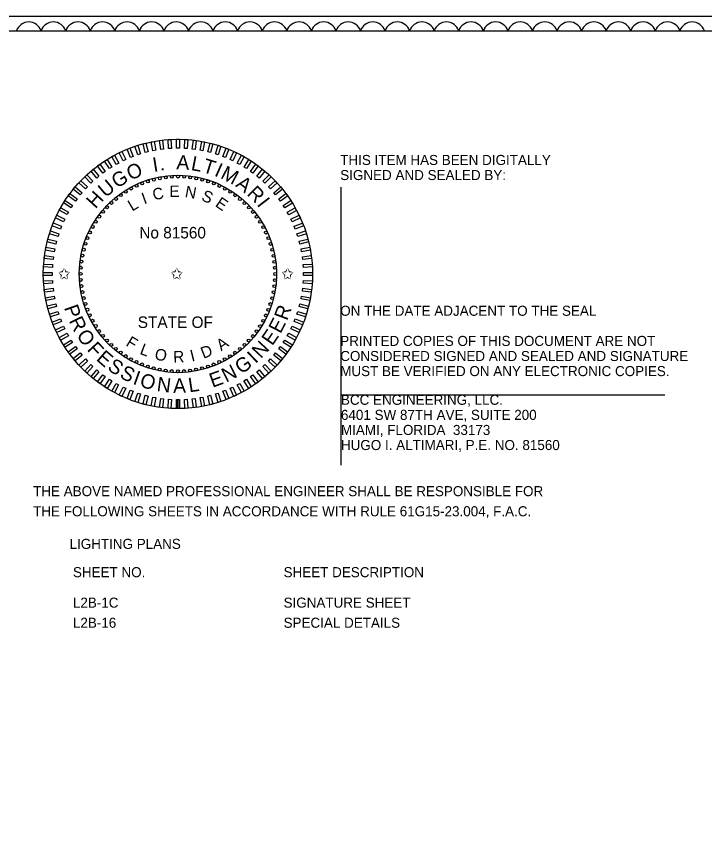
# Model space of a CAD drawing. Extents: x -811.3 to -790.1, y -2211.9 to -2188.9.
# Drawn here: x -802.91 to -798.12, y -2207.1 to -2201.34 of the extents above; entities that cross this region are included whole.
import ezdxf

# ---------------------------------------------------------------- set-up
doc = ezdxf.new("R2010")
doc.units = 0
for name, color, linetype in [('Cloud_dp', 7, 'Continuous'), ('Logo_dp', 7, 'Continuous'), ('NonPlottingEle_dp', 7, 'Continuous'), ('PlotBorder_dp', 7, 'Continuous'), ('ScratchEle_dp', 7, 'Continuous'), ('SheetBorder_dp', 7, 'Continuous'), ('TextMisc', 7, 'Continuous'), ('TextNotes', 7, 'Continuous')]:
    doc.layers.add(name, color=color, linetype=linetype)

msp = doc.modelspace()

# ---------------------------------------------------------------- linework, layer by layer
at = {"layer": 'Cloud_dp'}
for centre in [(-802.8286, -2201.467), (-802.6575, -2201.467), (-802.4863, -2201.467), (-802.3152, -2201.467), (-802.1441, -2201.467), (-801.973, -2201.467), (-801.8018, -2201.467), (-801.6307, -2201.467), (-801.4596, -2201.467), (-801.2885, -2201.467), (-801.1174, -2201.467), (-800.9462, -2201.467), (-800.7751, -2201.467), (-800.604, -2201.467), (-800.4329, -2201.467), (-800.2617, -2201.467), (-800.0906, -2201.467), (-799.9195, -2201.467), (-799.7484, -2201.467), (-799.5772, -2201.467), (-799.4061, -2201.467), (-799.235, -2201.467), (-799.0639, -2201.467), (-798.8928, -2201.467), (-798.7216, -2201.467), (-798.5505, -2201.467), (-798.3794, -2201.467), (-798.2083, -2201.467)]:
    msp.add_arc(centre, 0.0897, 17.5, 162.5, dxfattribs=at)
at = {"layer": 'Logo_dp'}
for p, q in [((-801.8001, -2204.0695), (-801.8003, -2204.007)), ((-801.7901, -2204.0695), (-801.7903, -2204.007)), ((-801.7801, -2204.0695), (-801.7803, -2204.007))]:
    msp.add_line(p, q, dxfattribs=at)
for points in [[(-801.8897, -2202.2626), (-801.9097, -2202.2651), (-801.9175, -2202.2032), (-801.8975, -2202.2007)], [(-801.8349, -2202.2581), (-801.855, -2202.2593), (-801.859, -2202.197), (-801.8388, -2202.1957)], [(-801.7799, -2202.257), (-801.8001, -2202.257), (-801.8001, -2202.1945), (-801.7799, -2202.1945)], [(-801.725, -2202.2593), (-801.7452, -2202.2581), (-801.7412, -2202.1958), (-801.7211, -2202.197)], [(-801.6703, -2202.2652), (-801.6904, -2202.2626), (-801.6825, -2202.2007), (-801.6625, -2202.2032)], [(-802.1028, -2202.3147), (-802.1215, -2202.3221), (-802.1445, -2202.2641), (-802.1258, -2202.2566)], [(-802.0508, -2202.2967), (-802.07, -2202.3029), (-802.0893, -2202.2435), (-802.0701, -2202.2373)], [(-801.9979, -2202.2819), (-802.0174, -2202.287), (-802.0329, -2202.2265), (-802.0134, -2202.2215)], [(-801.9441, -2202.2706), (-801.9639, -2202.2743), (-801.9756, -2202.213), (-801.9558, -2202.2092)], [(-801.6162, -2202.2744), (-801.636, -2202.2706), (-801.6243, -2202.2093), (-801.6045, -2202.2131)], [(-801.5626, -2202.287), (-801.5822, -2202.282), (-801.5667, -2202.2215), (-801.5471, -2202.2265)], [(-801.51, -2202.303), (-801.5292, -2202.2967), (-801.5099, -2202.2373), (-801.4907, -2202.2436)], [(-801.4585, -2202.3222), (-801.4773, -2202.3147), (-801.4543, -2202.2567), (-801.4355, -2202.2641)], [(-802.2027, -2202.3603), (-802.2204, -2202.37), (-802.2505, -2202.3153), (-802.2328, -2202.3056)], [(-802.1535, -2202.3359), (-802.1717, -2202.3445), (-802.1983, -2202.288), (-802.1801, -2202.2794)], [(-801.4083, -2202.3446), (-801.4266, -2202.336), (-801.4, -2202.2795), (-801.3817, -2202.2881)], [(-801.3596, -2202.3701), (-801.3773, -2202.3604), (-801.3473, -2202.3057), (-801.3296, -2202.3154)], [(-802.2962, -2202.4181), (-802.3125, -2202.43), (-802.3492, -2202.3795), (-802.3329, -2202.3676)], [(-802.2504, -2202.3877), (-802.2674, -2202.3986), (-802.3009, -2202.3458), (-802.2838, -2202.335)], [(-801.3127, -2202.3987), (-801.3297, -2202.3878), (-801.2962, -2202.3351), (-801.2792, -2202.3459)], [(-801.2676, -2202.4301), (-801.2839, -2202.4182), (-801.2472, -2202.3677), (-801.2308, -2202.3796)], [(-802.34, -2202.4513), (-802.3556, -2202.4642), (-802.3954, -2202.416), (-802.3798, -2202.4032)], [(-801.2245, -2202.4643), (-801.2401, -2202.4514), (-801.2003, -2202.4033), (-801.1847, -2202.4162)], [(-802.421, -2202.5256), (-802.4348, -2202.5403), (-802.4804, -2202.4976), (-802.4665, -2202.4828)], [(-802.3817, -2202.4872), (-802.3964, -2202.501), (-802.4392, -2202.4555), (-802.4244, -2202.4416)], [(-801.1837, -2202.5011), (-801.1984, -2202.4873), (-801.1557, -2202.4418), (-801.141, -2202.4556)], [(-801.1453, -2202.5404), (-801.1591, -2202.5257), (-801.1136, -2202.483), (-801.0998, -2202.4977)], [(-802.4579, -2202.5664), (-802.4707, -2202.5819), (-802.5188, -2202.5421), (-802.506, -2202.5266)], [(-801.1094, -2202.5821), (-801.1223, -2202.5665), (-801.0742, -2202.5267), (-801.0613, -2202.5423)], [(-802.492, -2202.6094), (-802.5039, -2202.6258), (-802.5544, -2202.5891), (-802.5426, -2202.5727)], [(-801.0762, -2202.6259), (-801.0881, -2202.6096), (-801.0376, -2202.5729), (-801.0257, -2202.5892)], [(-802.5235, -2202.6545), (-802.5343, -2202.6716), (-802.587, -2202.6381), (-802.5762, -2202.6211)], [(-801.0459, -2202.6717), (-801.0567, -2202.6547), (-801.0039, -2202.6212), (-800.9931, -2202.6383)], [(-802.5775, -2202.7502), (-802.5861, -2202.7685), (-802.6426, -2202.7419), (-802.634, -2202.7236)], [(-802.552, -2202.7015), (-802.5617, -2202.7192), (-802.6164, -2202.6891), (-802.6067, -2202.6715)], [(-801.0184, -2202.7194), (-801.0281, -2202.7017), (-800.9734, -2202.6716), (-800.9637, -2202.6893)], [(-800.994, -2202.7687), (-801.0026, -2202.7504), (-800.9461, -2202.7238), (-800.9375, -2202.7421)], [(-802.6, -2202.8004), (-802.6074, -2202.8192), (-802.6654, -2202.7962), (-802.658, -2202.7774)], [(-800.9728, -2202.8194), (-800.9802, -2202.8006), (-800.9222, -2202.7776), (-800.9147, -2202.7964)], [(-802.6192, -2202.8519), (-802.6254, -2202.8711), (-802.6848, -2202.8518), (-802.6786, -2202.8326)], [(-800.9548, -2202.8713), (-800.961, -2202.8521), (-800.9016, -2202.8328), (-800.8954, -2202.852)], [(-802.6351, -2202.9045), (-802.6401, -2202.9241), (-802.7006, -2202.9086), (-802.6956, -2202.889)], [(-800.94, -2202.9243), (-800.9451, -2202.9047), (-800.8846, -2202.8892), (-800.8796, -2202.9087)], [(-802.6477, -2202.958), (-802.6515, -2202.9779), (-802.7129, -2202.9662), (-802.7091, -2202.9463)], [(-800.9287, -2202.978), (-800.9325, -2202.9582), (-800.8711, -2202.9465), (-800.8673, -2202.9663)], [(-802.657, -2203.0122), (-802.6595, -2203.0323), (-802.7215, -2203.0244), (-802.7189, -2203.0044)], [(-800.9207, -2203.0324), (-800.9232, -2203.0124), (-800.8613, -2203.0046), (-800.8588, -2203.0246)], [(-802.6628, -2203.0669), (-802.6641, -2203.087), (-802.7264, -2203.0831), (-802.7251, -2203.063)], [(-800.9162, -2203.0872), (-800.9174, -2203.0671), (-800.8551, -2203.0632), (-800.8539, -2203.0833)], [(-802.6652, -2203.1218), (-802.6652, -2203.142), (-802.7276, -2203.142), (-802.7276, -2203.1218)], [(-800.9151, -2203.1422), (-800.9151, -2203.122), (-800.8527, -2203.122), (-800.8527, -2203.1422)], [(-802.6641, -2203.1768), (-802.6628, -2203.1969), (-802.7251, -2203.2009), (-802.7264, -2203.1807)], [(-800.9175, -2203.1971), (-800.9162, -2203.177), (-800.8539, -2203.1809), (-800.8551, -2203.201)], [(-802.6595, -2203.2316), (-802.657, -2203.2516), (-802.7189, -2203.2594), (-802.7215, -2203.2394)], [(-800.9233, -2203.2518), (-800.9207, -2203.2318), (-800.8588, -2203.2396), (-800.8613, -2203.2596)], [(-802.6516, -2203.286), (-802.6478, -2203.3058), (-802.7091, -2203.3175), (-802.7129, -2203.2977)], [(-800.9325, -2203.306), (-800.9287, -2203.2861), (-800.8674, -2203.2978), (-800.8712, -2203.3177)], [(-802.6402, -2203.3398), (-802.6352, -2203.3593), (-802.6957, -2203.3748), (-802.7007, -2203.3553)], [(-800.9451, -2203.3595), (-800.9401, -2203.3399), (-800.8796, -2203.3555), (-800.8846, -2203.375)], [(-802.6255, -2203.3927), (-802.6192, -2203.4119), (-802.6786, -2203.4312), (-802.6849, -2203.412)], [(-800.9611, -2203.4121), (-800.9548, -2203.3929), (-800.8954, -2203.4122), (-800.9017, -2203.4314)], [(-802.6075, -2203.4447), (-802.6, -2203.4634), (-802.6581, -2203.4864), (-802.6655, -2203.4676)], [(-800.9803, -2203.4636), (-800.9729, -2203.4448), (-800.9148, -2203.4678), (-800.9222, -2203.4866)], [(-802.5862, -2203.4954), (-802.5776, -2203.5136), (-802.6341, -2203.5402), (-802.6427, -2203.5219)], [(-801.0027, -2203.5138), (-800.9941, -2203.4955), (-800.9376, -2203.5221), (-800.9462, -2203.5404)], [(-802.5618, -2203.5446), (-802.5521, -2203.5623), (-802.6068, -2203.5924), (-802.6165, -2203.5747)], [(-801.0282, -2203.5625), (-801.0185, -2203.5448), (-800.9638, -2203.5749), (-800.9735, -2203.5926)], [(-802.5344, -2203.5923), (-802.5236, -2203.6093), (-802.5763, -2203.6428), (-802.5871, -2203.6257)], [(-802.504, -2203.6381), (-802.4922, -2203.6544), (-802.5427, -2203.6911), (-802.5545, -2203.6748)], [(-801.0882, -2203.6546), (-801.0763, -2203.6382), (-801.0258, -2203.6749), (-801.0377, -2203.6913)], [(-801.0568, -2203.6095), (-801.046, -2203.5924), (-800.9932, -2203.6259), (-801.004, -2203.6429)], [(-802.4708, -2203.6819), (-802.458, -2203.6975), (-802.5061, -2203.7373), (-802.5189, -2203.7217)], [(-801.1224, -2203.6976), (-801.1095, -2203.6821), (-801.0614, -2203.7219), (-801.0743, -2203.7374)], [(-802.435, -2203.7236), (-802.4211, -2203.7383), (-802.4667, -2203.781), (-802.4805, -2203.7663)], [(-801.1592, -2203.7384), (-801.1454, -2203.7237), (-801.0999, -2203.7665), (-801.1137, -2203.7812)], [(-802.3965, -2203.7629), (-802.3818, -2203.7767), (-802.4246, -2203.8222), (-802.4393, -2203.8084)], [(-802.3557, -2203.7997), (-802.3402, -2203.8126), (-802.38, -2203.8607), (-802.3955, -2203.8478)], [(-801.2402, -2203.8127), (-801.2247, -2203.7999), (-801.1848, -2203.848), (-801.2004, -2203.8608)], [(-801.1985, -2203.7768), (-801.1838, -2203.763), (-801.1411, -2203.8085), (-801.1558, -2203.8224)], [(-802.3127, -2203.8339), (-802.2964, -2203.8458), (-802.3331, -2203.8963), (-802.3494, -2203.8844)], [(-802.2676, -2203.8654), (-802.2505, -2203.8762), (-802.284, -2203.9289), (-802.301, -2203.9181)], [(-801.3299, -2203.8763), (-801.3128, -2203.8655), (-801.2794, -2203.9182), (-801.2964, -2203.929)], [(-801.284, -2203.8459), (-801.2677, -2203.834), (-801.231, -2203.8846), (-801.2473, -2203.8964)], [(-802.2206, -2203.8939), (-802.2029, -2203.9036), (-802.233, -2203.9583), (-802.2507, -2203.9486)], [(-802.1719, -2203.9194), (-802.1536, -2203.928), (-802.1802, -2203.9845), (-802.1985, -2203.9759)], [(-801.4268, -2203.9281), (-801.4085, -2203.9195), (-801.3819, -2203.976), (-801.4002, -2203.9846)], [(-801.3775, -2203.9037), (-801.3598, -2203.894), (-801.3297, -2203.9487), (-801.3474, -2203.9584)], [(-802.1217, -2203.9418), (-802.1029, -2203.9493), (-802.1259, -2204.0073), (-802.1447, -2203.9999)], [(-802.0702, -2203.9611), (-802.051, -2203.9673), (-802.0703, -2204.0267), (-802.0895, -2204.0204)], [(-802.0176, -2203.977), (-801.998, -2203.982), (-802.0136, -2204.0425), (-802.0331, -2204.0375)], [(-801.9641, -2203.9896), (-801.9443, -2203.9934), (-801.956, -2204.0547), (-801.9758, -2204.051)], [(-801.6362, -2203.9934), (-801.6163, -2203.9897), (-801.6046, -2204.051), (-801.6245, -2204.0548)], [(-801.5824, -2203.9821), (-801.5628, -2203.9771), (-801.5473, -2204.0375), (-801.5668, -2204.0426)], [(-801.5294, -2203.9674), (-801.5102, -2203.9611), (-801.4909, -2204.0205), (-801.5101, -2204.0267)], [(-801.4775, -2203.9493), (-801.4587, -2203.9419), (-801.4357, -2204), (-801.4545, -2204.0074)], [(-801.9099, -2203.9989), (-801.8899, -2204.0014), (-801.8977, -2204.0633), (-801.9177, -2204.0608)], [(-801.8552, -2204.0047), (-801.8351, -2204.0059), (-801.839, -2204.0683), (-801.8592, -2204.067)], [(-801.8003, -2204.007), (-801.7801, -2204.007), (-801.7801, -2204.0695), (-801.8003, -2204.0695)], [(-801.7453, -2204.0059), (-801.7252, -2204.0047), (-801.7213, -2204.067), (-801.7414, -2204.0683)], [(-801.6906, -2204.0014), (-801.6705, -2203.9989), (-801.6627, -2204.0608), (-801.6827, -2204.0634)]]:
    msp.add_lwpolyline(points, close=True, dxfattribs=at)
for centre in [(-802.039, -2202.5019), (-801.9989, -2202.4875), (-801.9581, -2202.4757), (-801.9165, -2202.4664), (-801.8745, -2202.4598), (-801.8321, -2202.4558), (-801.7896, -2202.4545), (-801.747, -2202.4559), (-801.7047, -2202.46), (-801.6626, -2202.4666), (-801.6211, -2202.476), (-801.5802, -2202.4879), (-801.5402, -2202.5023), (-802.1527, -2202.5597), (-802.116, -2202.5381), (-802.0781, -2202.5188), (-801.5012, -2202.5193), (-801.4633, -2202.5386), (-801.4266, -2202.5603), (-802.2215, -2202.6096), (-802.1879, -2202.5836), (-801.3915, -2202.5843), (-801.3579, -2202.6104), (-802.2836, -2202.6678), (-802.2535, -2202.6378), (-801.326, -2202.6385), (-801.2959, -2202.6687), (-802.3379, -2202.7333), (-802.3118, -2202.6997), (-801.2678, -2202.7006), (-801.2417, -2202.7343), (-802.3618, -2202.7685), (-801.2178, -2202.7695), (-802.4029, -2202.843), (-802.3835, -2202.8051), (-801.1962, -2202.8061), (-801.1769, -2202.8441), (-802.4198, -2202.8821), (-801.16, -2202.8831), (-802.4462, -2202.963), (-802.4343, -2202.9221), (-801.1456, -2202.9232), (-801.1338, -2202.9641), (-802.4555, -2203.0045), (-801.1245, -2203.0056), (-802.4622, -2203.0465), (-801.1179, -2203.0477), (-802.4676, -2203.1314), (-802.4662, -2203.0889), (-801.114, -2203.09), (-801.1127, -2203.1326), (-802.4663, -2203.174), (-801.114, -2203.1751), (-802.4623, -2203.2164), (-801.1181, -2203.2175), (-802.4557, -2203.2584), (-802.4464, -2203.2999), (-801.1341, -2203.301), (-801.1248, -2203.2595), (-802.4346, -2203.3408), (-801.146, -2203.3419), (-802.4202, -2203.3809), (-802.4034, -2203.4199), (-801.1774, -2203.421), (-801.1604, -2203.3819), (-802.3841, -2203.4579), (-801.1967, -2203.4589), (-802.3624, -2203.4945), (-802.3385, -2203.5298), (-801.2424, -2203.5307), (-801.2184, -2203.4955), (-802.3125, -2203.5634), (-802.2844, -2203.5954), (-801.2967, -2203.5962), (-801.2685, -2203.5643), (-802.2543, -2203.6255), (-802.2224, -2203.6536), (-801.3587, -2203.6544), (-801.3268, -2203.6262), (-802.1888, -2203.6798), (-802.1536, -2203.7037), (-801.4276, -2203.7043), (-801.3924, -2203.6804), (-802.117, -2203.7254), (-802.0791, -2203.7448), (-802.04, -2203.7617), (-801.5413, -2203.7621), (-801.5022, -2203.7452), (-801.4642, -2203.7259), (-802, -2203.7761), (-801.9591, -2203.7881), (-801.9176, -2203.7974), (-801.8756, -2203.8041), (-801.8332, -2203.8081), (-801.7901, -2203.8095), (-801.7481, -2203.8082), (-801.7058, -2203.8042), (-801.6637, -2203.7976), (-801.6222, -2203.7883), (-801.5813, -2203.7765)]:
    msp.add_circle(centre, 0.01, dxfattribs=at)
at = {"layer": 'NonPlottingEle_dp'}
for radius in [0.9375, 0.6875]:
    msp.add_circle((-801.7901, -2203.132), radius, dxfattribs=at)
at = {"layer": 'PlotBorder_dp'}
msp.add_lwpolyline([(-811.3358, -2211.9401), (-794.8358, -2211.9401), (-794.8358, -2201.3401), (-811.3358, -2201.3401)], close=True, dxfattribs=at)
at = {"layer": 'ScratchEle_dp'}
for p, q in [((-800.6546, -2202.5286), (-800.6546, -2204.4633)), ((-800.6546, -2203.9733), (-798.3979, -2203.9733))]:
    msp.add_line(p, q, dxfattribs=at)
at = {"layer": 'SheetBorder_dp'}
msp.add_line((-810.7858, -2201.4401), (-795.3858, -2201.4401), dxfattribs=at)

# ---------------------------------------------------------------- texts
at = {"layer": 'Logo_dp'}
for s, height, rotation, p in [('I', 0.1, 9.19839, (-801.9584, -2202.4223)), ('A', 0.1, 356.81106, (-801.8022, -2202.4027)), ('L', 0.1, 349.04407, (-801.7035, -2202.4078)), ('O', 0.1, 22.93861, (-802.1221, -2202.4826)), ('T', 0.1, 342.78095, (-801.625, -2202.4215)), ('I', 0.1, 335.95614, (-801.5418, -2202.4462)), ('G', 0.1, 31.47264, (-802.2148, -2202.539)), ('.', 0.1, 5.6652, (-801.9143, -2202.4133)), ('M', 0.1, 332.42294, (-801.5, -2202.4628)), ('U', 0.1, 39.55973, (-802.294, -2202.6047)), ('A', 0.1, 322.97692, (-801.3941, -2202.5195)), ('C', 0.08, 12.20255, (-801.9579, -2202.6204)), ('E', 0.08, 0.41861, (-801.8498, -2202.5969)), ('N', 0.08, 349.29143, (-801.7455, -2202.5955)), ('S', 0.08, 337.02207, (-801.6325, -2202.6172)), ('R', 0.1, 315.20993, (-801.315, -2202.5786)), ('H', 0.1, 47.85218, (-802.3648, -2202.6829)), ('I', 0.08, 20.01168, (-802.0258, -2202.6479)), ('E', 0.08, 325.86633, (-801.5358, -2202.6574)), ('I', 0.1, 307.38858, (-801.2441, -2202.6484)), ('L', 0.08, 30.40215, (-802.1093, -2202.6984)), ('P', 0.1, 289.40551, (-802.5848, -2203.3666)), ('R', 0.1, 69.5134, (-801.0299, -2203.4617)), ('R', 0.1, 296.14576, (-802.5518, -2203.4582)), ('E', 0.1, 62.47116, (-801.0761, -2203.5524)), ('O', 0.1, 303.96711, (-802.5003, -2203.5589)), ('E', 0.1, 55.42892, (-801.133, -2203.6368)), ('F', 0.08, 328.72408, (-802.1582, -2203.6286)), ('A', 0.08, 34.49917, (-801.4883, -2203.6714)), ('F', 0.1, 312.62798, (-802.4279, -2203.6609)), ('L', 0.08, 339.29159, (-802.0609, -2203.6877)), ('D', 0.08, 22.01279, (-801.612, -2203.7239)), ('N', 0.1, 47.17876, (-801.2123, -2203.7259)), ('E', 0.1, 319.07833, (-802.3645, -2203.7292)), ('O', 0.08, 349.68206, (-801.9562, -2203.7274)), ('R', 0.08, 2.33977, (-801.8217, -2203.7493)), ('I', 0.08, 14.20366, (-801.6941, -2203.7426)), ('I', 0.1, 43.64556, (-801.2499, -2203.7603)), ('S', 0.1, 326.12056, (-802.2869, -2203.7952)), ('N', 0.1, 26.86136, (-801.4544, -2203.8896)), ('G', 0.1, 35.11153, (-801.3492, -2203.8335)), ('S', 0.1, 333.193, (-802.2015, -2203.8513)), ('I', 0.1, 340.26543, (-802.1098, -2203.8965)), ('E', 0.1, 19.81912, (-801.5498, -2203.925)), ('O', 0.1, 343.79863, (-802.0621, -2203.9147)), ('N', 0.1, 352.45949, (-801.9411, -2203.9467)), ('A', 0.1, 0.70966, (-801.8227, -2203.96)), ('L', 0.1, 8.47665, (-801.7105, -2203.9568))]:
    msp.add_text(s, height=height, rotation=rotation, dxfattribs=at).set_placement(p)
for s, p in [('No 81560', (-802.0591, -2202.8848)), ('✩', (-802.6251, -2203.17)), ('✩', (-801.8404, -2203.17)), ('✩', (-801.0685, -2203.17)), ('STATE OF', (-802.0698, -2203.5082))]:
    msp.add_text(s, height=0.08, dxfattribs=at).set_placement(p)
at = {"layer": 'TextMisc'}
for s, p in [('THIS ITEM HAS BEEN DIGITALLY', (-800.6596, -2202.3735)), ('SIGNED AND SEALED BY:', (-800.6596, -2202.4785)), ('ON THE DATE ADJACENT TO THE SEAL', (-800.6596, -2203.4235)), ('PRINTED COPIES OF THIS DOCUMENT ARE NOT ', (-800.6596, -2203.6335)), ('CONSIDERED SIGNED AND SEALED AND SIGNATURE ', (-800.6596, -2203.7385)), ('MUST BE VERIFIED ON ANY ELECTRONIC COPIES.', (-800.6596, -2203.8435)), ('BCC ENGINEERING, LLC.', (-800.6546, -2204.0433)), ('6401 SW 87TH AVE, SUITE 200', (-800.6546, -2204.1483)), ('MIAMI, FLORIDA  33173', (-800.6546, -2204.2533)), ('HUGO I. ALTIMARI, P.E. NO. 81560', (-800.6546, -2204.3583)), ('THE ABOVE NAMED PROFESSIONAL ENGINEER SHALL BE RESPONSIBLE FOR ', (-802.7987, -2204.6794)), ('THE FOLLOWING SHEETS IN ACCORDANCE WITH RULE 61G15-23.004, F.A.C.', (-802.7987, -2204.8194)), ('LIGHTING PLANS', (-802.545, -2205.0465))]:
    msp.add_text(s, height=0.07, dxfattribs=at).set_placement(p)
at = {"layer": 'TextNotes'}
for s, p in [('SHEET NO.', (-802.5215, -2205.2435)), ('SHEET DESCRIPTION', (-801.0542, -2205.2435)), ('L2B-1C', (-802.5215, -2205.4557)), ('SIGNATURE SHEET', (-801.0542, -2205.4557)), ('L2B-16', (-802.5215, -2205.5957)), ('SPECIAL DETAILS', (-801.0542, -2205.5957))]:
    msp.add_text(s, height=0.07, dxfattribs=at).set_placement(p)

doc.saveas('drawing.dxf')
